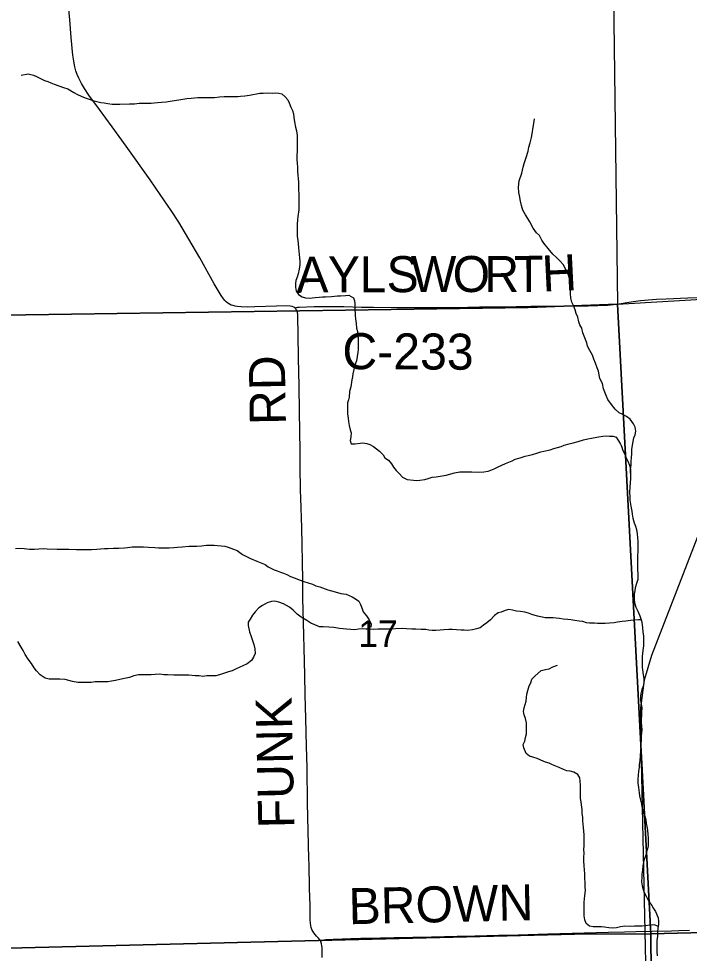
# Model space of a CAD drawing. Extents: x 0 to 34, y 0 to 22.
# Drawn here: x 4.5 to 5.557, y 15.347 to 16.821 of the extents above; entities that cross this region are included whole.
import ezdxf

# ---------------------------------------------------------------- set-up
doc = ezdxf.new("R2010")
doc.units = 0
for name, color, linetype in [('GM_X_County_Road', 7, 'Continuous'), ('GM_X_County_Road_Text', 7, 'Continuous'), ('GM_X_Minor_River', 7, 'Continuous'), ('GM_X_Rail_Line', 7, 'Continuous'), ('GM_X_Section', 7, 'Continuous'), ('GM_X_Section_Text', 7, 'Continuous'), ('GM_X_Township_Road', 7, 'Continuous'), ('GM_X_Township_Road_Text', 7, 'Continuous')]:
    doc.layers.add(name, color=color, linetype=linetype)

msp = doc.modelspace()

# ---------------------------------------------------------------- linework, layer by layer
at = {"layer": 'GM_X_County_Road'}
for points in [[(4.9354, 16.3647), (4.9339, 16.3655), (4.9312, 16.3666), (4.9283, 16.3672), (4.9222, 16.3676), (4.9066, 16.3673), (4.8725, 16.3662), (4.86, 16.3659), (4.8506, 16.3662), (4.8443, 16.3667), (4.8412, 16.3673), (4.8382, 16.3681), (4.8352, 16.3691), (4.8323, 16.3705), (4.8296, 16.3722), (4.8271, 16.3741), (4.8248, 16.3764), (4.8228, 16.3787), (4.8191, 16.3839), (4.8143, 16.3919), (4.8081, 16.4027), (4.7854, 16.4434), (4.7684, 16.473), (4.7523, 16.4996), (4.7406, 16.5179), (4.7232, 16.5436), (4.7072, 16.5665), (4.6693, 16.6197), (4.6475, 16.65), (4.6275, 16.6777), (4.6108, 16.7001), (4.6038, 16.7105), (4.599, 16.7186), (4.5948, 16.7269), (4.5923, 16.7327), (4.5903, 16.7386), (4.5886, 16.7446), (4.5867, 16.7538), (4.5854, 16.7631), (4.5828, 16.791), (4.5805, 16.8188), (4.5781, 16.8467)], [(4.9354, 16.3647), (4.9376, 16.3652), (4.9396, 16.3655), (4.9425, 16.3658), (4.9661, 16.3666), (5.0127, 16.3665), (5.0407, 16.3659), (5.0593, 16.3656), (5.0965, 16.3652), (5.112, 16.365), (5.1369, 16.365), (5.1555, 16.3651), (5.1802, 16.3654), (5.2082, 16.3658), (5.2268, 16.3661), (5.261, 16.3664), (5.3076, 16.3671), (5.3449, 16.3672), (5.3822, 16.3676), (5.3977, 16.3677), (5.4132, 16.3681), (5.4286, 16.3688), (5.4378, 16.3697), (5.447, 16.3709), (5.4623, 16.3734), (5.4807, 16.3762), (5.4931, 16.3775), (5.5055, 16.3783), (5.521, 16.3791), (5.5551, 16.3803), (5.5707, 16.3808)], [(4.9757, 15.3662), (4.9749, 15.3677), (4.9728, 15.3703), (4.9694, 15.3737), (4.9673, 15.3761), (4.9654, 15.3787), (4.9637, 15.3814), (4.9624, 15.3843), (4.9614, 15.3873), (4.9607, 15.3904), (4.9602, 15.3936), (4.9598, 15.3998), (4.9595, 15.4216), (4.9587, 15.4496), (4.9578, 15.4868), (4.9575, 15.4962), (4.9563, 15.5396), (4.9556, 15.5832), (4.9547, 15.6391), (4.9537, 15.6733), (4.9528, 15.7168), (4.9518, 15.7541), (4.9511, 15.7851), (4.9501, 15.8286), (4.9496, 15.8472), (4.9492, 15.869), (4.9488, 15.8876), (4.9481, 15.9063), (4.9479, 15.9342), (4.9476, 15.9653), (4.9469, 15.9902), (4.9462, 16.0181), (4.9448, 16.0646), (4.9446, 16.077), (4.944, 16.1143), (4.9439, 16.1392), (4.9433, 16.1703), (4.9427, 16.2013), (4.942, 16.2417), (4.9412, 16.2852), (4.9406, 16.3225), (4.9403, 16.3505), (4.94, 16.3548), (4.9397, 16.3564), (4.9394, 16.3579), (4.939, 16.3597), (4.9382, 16.3614), (4.9373, 16.3627), (4.9362, 16.364), (4.9354, 16.3647)], [(4.9786, 15.3399), (4.9786, 15.3521), (4.9785, 15.3558), (4.9782, 15.3586), (4.9776, 15.3616), (4.9764, 15.365), (4.9757, 15.3662)]]:
    msp.add_lwpolyline(points, dxfattribs=at)
at = {"layer": 'GM_X_Minor_River'}
for points in [[(4.5037, 16.7314), (4.5151, 16.7337), (4.5231, 16.7314), (4.5289, 16.7291), (4.5342, 16.7264), (4.5407, 16.7234), (4.546, 16.7218), (4.5506, 16.7196), (4.556, 16.7173), (4.5632, 16.7146), (4.5709, 16.7119), (4.5774, 16.71), (4.5869, 16.7043), (4.5927, 16.7013), (4.5984, 16.6986), (4.6049, 16.696), (4.611, 16.6937), (4.6171, 16.6918), (4.6293, 16.6887), (4.6347, 16.688), (4.6404, 16.6868), (4.6473, 16.6857), (4.6595, 16.6857), (4.6747, 16.6864), (4.6824, 16.6864), (4.69, 16.6872), (4.6969, 16.6875), (4.7087, 16.6875), (4.7137, 16.6879), (4.719, 16.6883), (4.7251, 16.689), (4.7327, 16.6898), (4.7419, 16.6913), (4.7526, 16.6925), (4.7652, 16.6947), (4.772, 16.6955), (4.7827, 16.6962), (4.809, 16.6962), (4.8167, 16.6974), (4.8239, 16.6977), (4.8323, 16.6977), (4.8392, 16.6981), (4.8453, 16.6981), (4.8499, 16.6985), (4.8564, 16.6992), (4.864, 16.7), (4.869, 16.7011), (4.8751, 16.7023), (4.88, 16.703), (4.8854, 16.7034), (4.8945, 16.7038), (4.9006, 16.7034), (4.9056, 16.7038), (4.9102, 16.703), (4.9151, 16.7019), (4.9201, 16.6973), (4.9243, 16.6927), (4.9266, 16.6882), (4.9289, 16.6813), (4.9316, 16.676), (4.9335, 16.6707), (4.9339, 16.665), (4.9347, 16.6581), (4.9362, 16.6498), (4.9378, 16.6437), (4.9389, 16.6364), (4.939, 16.6247), (4.939, 16.619), (4.939, 16.6121), (4.9386, 16.6045), (4.9386, 16.5999), (4.939, 16.592), (4.9394, 16.5874), (4.9398, 16.5798), (4.941, 16.5627), (4.9414, 16.5562), (4.9415, 16.5391), (4.9419, 16.5338), (4.9419, 16.5262), (4.9415, 16.5193), (4.9404, 16.5087), (4.9396, 16.5034), (4.9393, 16.4965), (4.9393, 16.4908), (4.9389, 16.4843), (4.9393, 16.4775), (4.9401, 16.4707), (4.9409, 16.4661), (4.9413, 16.4592), (4.9417, 16.4539), (4.9421, 16.449), (4.9428, 16.4433), (4.9432, 16.4379), (4.9432, 16.433), (4.9421, 16.4258), (4.9406, 16.4182), (4.9391, 16.4129), (4.9372, 16.4075), (4.9364, 16.403), (4.9365, 16.3973), (4.9376, 16.3912)], [(5.4649, 16.1038), (5.4645, 16.1106), (5.4657, 16.1163), (5.466, 16.122), (5.4664, 16.1289), (5.4668, 16.1338), (5.4668, 16.141), (5.4679, 16.1479), (5.469, 16.154), (5.4701, 16.1597), (5.472, 16.1646), (5.4732, 16.1703), (5.472, 16.1764), (5.4693, 16.1817), (5.4644, 16.189), (5.4582, 16.1935), (5.4525, 16.1962), (5.4468, 16.1992), (5.4403, 16.2049), (5.4349, 16.2122), (5.4292, 16.2202), (5.4261, 16.2262), (5.4242, 16.2316), (5.4219, 16.2369), (5.4203, 16.2453), (5.4165, 16.2533), (5.4153, 16.259), (5.4142, 16.265), (5.4123, 16.27), (5.4096, 16.2772), (5.4069, 16.2837), (5.4046, 16.2898), (5.4007, 16.2974), (5.3969, 16.3042), (5.3958, 16.3095), (5.3938, 16.3149), (5.3915, 16.3198), (5.3896, 16.3251), (5.3877, 16.3324), (5.3846, 16.3377), (5.3831, 16.3426), (5.3815, 16.3499), (5.3792, 16.3559), (5.3777, 16.3613), (5.3746, 16.3685), (5.3723, 16.3734), (5.3708, 16.3799), (5.37, 16.3871), (5.37, 16.3951), (5.3696, 16.4027), (5.3684, 16.4111), (5.3669, 16.416), (5.3642, 16.4214), (5.3623, 16.4263), (5.3585, 16.4331), (5.3539, 16.4381), (5.3481, 16.4442), (5.3424, 16.4491), (5.3351, 16.4583), (5.3282, 16.4666), (5.3248, 16.4716), (5.3213, 16.4788), (5.3164, 16.483), (5.3114, 16.4902), (5.306, 16.5001), (5.3029, 16.5058), (5.2991, 16.5115), (5.2949, 16.5187), (5.2926, 16.526), (5.291, 16.5328), (5.2895, 16.5416), (5.2887, 16.5465), (5.2883, 16.5549), (5.2894, 16.5648), (5.2936, 16.5769), (5.2955, 16.5864), (5.297, 16.5925), (5.3004, 16.602), (5.3031, 16.6115), (5.3046, 16.618), (5.3065, 16.6248), (5.3087, 16.6332), (5.3099, 16.6389), (5.3114, 16.6495), (5.3121, 16.6556), (5.3133, 16.6625)], [(4.9376, 16.3912), (4.9414, 16.3859), (4.9468, 16.382), (4.9521, 16.3805), (4.9579, 16.3798), (4.9628, 16.3805), (4.9674, 16.3809), (4.9739, 16.3817), (4.9788, 16.382), (4.9838, 16.382), (4.993, 16.3824), (4.9979, 16.3828), (5.0029, 16.3835), (5.0075, 16.3835), (5.0155, 16.3843), (5.0204, 16.3847), (5.0277, 16.3805), (5.0296, 16.3759), (5.03, 16.371), (5.03, 16.3649), (5.0308, 16.3527), (5.0312, 16.3474), (5.032, 16.3398), (5.0328, 16.3326), (5.0343, 16.3272), (5.0347, 16.3219), (5.0351, 16.3155), (5.0355, 16.3109), (5.0355, 16.3056), (5.0351, 16.2991), (5.0348, 16.2945), (5.0336, 16.2881), (5.0325, 16.2809), (5.0302, 16.2744), (5.0287, 16.2675), (5.0268, 16.2603), (5.0261, 16.2558), (5.0253, 16.2512), (5.0235, 16.2398), (5.0216, 16.2329), (5.0212, 16.2238), (5.0201, 16.2193), (5.0185, 16.2147), (5.0186, 16.1976), (5.0194, 16.1904), (5.0201, 16.1854), (5.0213, 16.1789), (5.0228, 16.1725), (5.024, 16.1675), (5.0236, 16.1611), (5.0229, 16.1554), (5.0244, 16.1504), (5.0305, 16.15), (5.0382, 16.1512), (5.0427, 16.1516), (5.0488, 16.1508), (5.0538, 16.1489), (5.0595, 16.1462), (5.0687, 16.1386), (5.0748, 16.1329), (5.0775, 16.128), (5.0829, 16.1242), (5.0878, 16.1185), (5.0909, 16.1131), (5.0951, 16.1082), (5.0997, 16.1032), (5.1051, 16.0975), (5.1127, 16.0937), (5.1223, 16.0926), (5.128, 16.0922), (5.1326, 16.0926), (5.1402, 16.0937), (5.1459, 16.0956), (5.152, 16.0975), (5.1581, 16.0983), (5.1741, 16.1009), (5.1871, 16.1043), (5.1955, 16.1058), (5.2047, 16.1062), (5.2146, 16.1058), (5.2249, 16.1054), (5.2333, 16.1062), (5.2401, 16.1073), (5.2459, 16.1089), (5.2508, 16.1115), (5.2562, 16.1138), (5.2676, 16.1191), (5.2726, 16.121), (5.2783, 16.1233), (5.2828, 16.1259), (5.2905, 16.1282), (5.2985, 16.1305), (5.3034, 16.132), (5.3103, 16.1335), (5.3172, 16.1354), (5.3233, 16.1373), (5.3282, 16.1385), (5.3378, 16.1407), (5.3439, 16.1426), (5.3496, 16.1442), (5.3553, 16.1461)], [(5.3553, 16.1461), (5.3603, 16.148), (5.3679, 16.1499), (5.3744, 16.1517), (5.382, 16.1536), (5.3908, 16.1563), (5.3976, 16.1578), (5.403, 16.159), (5.4144, 16.1612), (5.4209, 16.1624), (5.427, 16.1627), (5.4316, 16.1624), (5.4373, 16.162), (5.4423, 16.1608), (5.4446, 16.1563), (5.4484, 16.1509), (5.4507, 16.1464), (5.4526, 16.1399), (5.4557, 16.1338), (5.4572, 16.1289), (5.4603, 16.1228), (5.463, 16.1167), (5.4645, 16.1095), (5.4649, 16.103), (5.4646, 16.0954), (5.4638, 16.0817), (5.4631, 16.0737), (5.4635, 16.0661), (5.4639, 16.0612), (5.4654, 16.0521), (5.4666, 16.0441), (5.4674, 16.0391), (5.4682, 16.0327), (5.4705, 16.0258), (5.4724, 16.0205), (5.4739, 16.0148), (5.4751, 16.0083), (5.4759, 16.0019), (5.4762, 15.9965), (5.4763, 15.981), (5.4759, 15.9737), (5.4759, 15.9692), (5.4756, 15.9604), (5.4756, 15.9536), (5.4764, 15.9437), (5.476, 15.9361), (5.4741, 15.93), (5.4722, 15.9228), (5.4715, 15.9182), (5.4707, 15.9129), (5.4704, 15.9053), (5.4711, 15.8992), (5.4731, 15.8924), (5.4761, 15.8863), (5.4796, 15.8787), (5.4819, 15.8711), (5.483, 15.8654), (5.4838, 15.8596), (5.4842, 15.8539), (5.485, 15.8467), (5.4854, 15.8399), (5.485, 15.8315), (5.4839, 15.8243), (5.4832, 15.8148), (5.4832, 15.798), (5.4836, 15.7935), (5.4848, 15.7859), (5.4859, 15.7802), (5.4859, 15.7749), (5.4852, 15.7691), (5.4825, 15.7627), (5.481, 15.7562), (5.4806, 15.7517), (5.4803, 15.7456), (5.4814, 15.7395), (5.4826, 15.7338), (5.4818, 15.7266), (5.4819, 15.7212), (5.4815, 15.7163), (5.4815, 15.711), (5.4819, 15.7049), (5.4823, 15.6992), (5.4819, 15.6946), (5.4815, 15.6889), (5.4816, 15.6825), (5.4812, 15.6775), (5.4808, 15.6718), (5.4805, 15.6669), (5.4797, 15.6577), (5.4793, 15.6509), (5.4786, 15.644), (5.4782, 15.6395), (5.4771, 15.6338), (5.4767, 15.6277), (5.4764, 15.6212), (5.4764, 15.6152), (5.4772, 15.6083), (5.4783, 15.5996), (5.4791, 15.595), (5.4806, 15.5882), (5.4818, 15.5821)], [(4.4951, 15.9853), (4.502, 15.9857), (4.5088, 15.9853), (4.5169, 15.9842), (4.5249, 15.9842), (4.5317, 15.9845), (4.5398, 15.9849), (4.5451, 15.9845), (4.5607, 15.9841), (4.568, 15.9838), (4.5791, 15.9841), (4.5909, 15.9837), (4.6146, 15.9837), (4.6233, 15.9841), (4.6291, 15.9845), (4.6355, 15.9852), (4.6405, 15.9852), (4.6497, 15.9856), (4.6577, 15.9856), (4.6668, 15.986), (4.6718, 15.9864), (4.6787, 15.9879), (4.6836, 15.9879), (4.6966, 15.9879), (4.7046, 15.9871), (4.7149, 15.9867), (4.7206, 15.986), (4.726, 15.9859), (4.7313, 15.9863), (4.7374, 15.9863), (4.7447, 15.9867), (4.7504, 15.9871), (4.758, 15.9878), (4.7687, 15.9886), (4.7809, 15.9886), (4.7882, 15.9893), (4.7962, 15.9901), (4.8027, 15.9905), (4.8084, 15.9905), (4.8134, 15.9897), (4.8191, 15.9893), (4.8248, 15.9886), (4.8302, 15.9874), (4.8386, 15.984), (4.8447, 15.9817), (4.8531, 15.9756), (4.8657, 15.9691), (4.8756, 15.9649), (4.8886, 15.9596), (4.8936, 15.9562), (4.9028, 15.9516), (4.9077, 15.9501), (4.9127, 15.9478), (4.9177, 15.9463), (4.923, 15.944), (4.9287, 15.941), (4.936, 15.9383), (4.9421, 15.9356), (4.9494, 15.9333), (4.9631, 15.9288), (4.9685, 15.9261), (4.975, 15.9246), (4.9876, 15.92), (4.9933, 15.9181), (5.0025, 15.9158), (5.0078, 15.9143), (5.0166, 15.9128), (5.0257, 15.909), (5.0311, 15.9059), (5.0361, 15.9021), (5.0391, 15.8968), (5.0411, 15.8915), (5.0434, 15.885), (5.0483, 15.8789), (5.0525, 15.8724), (5.0556, 15.866), (5.0552, 15.861)], [(5.4813, 15.8728), (5.4773, 15.8726), (5.4716, 15.8722), (5.4647, 15.8714), (5.4571, 15.8707), (5.4514, 15.8699), (5.4441, 15.8688), (5.4388, 15.8677), (5.4315, 15.8673), (5.4246, 15.8669), (5.4128, 15.8669), (5.4079, 15.8673), (5.4002, 15.8673), (5.3953, 15.8681), (5.3895, 15.87), (5.3838, 15.8707), (5.3769, 15.8715), (5.3708, 15.8726), (5.3659, 15.873), (5.3586, 15.8734), (5.3525, 15.8746), (5.3475, 15.8753), (5.3426, 15.8757), (5.33, 15.8757), (5.3231, 15.8772), (5.3181, 15.8784), (5.309, 15.881), (5.3036, 15.8829), (5.2983, 15.8845), (5.2914, 15.8856), (5.2849, 15.8864), (5.2788, 15.8879), (5.2727, 15.8887), (5.267, 15.8872), (5.2609, 15.8845), (5.2559, 15.8834), (5.2502, 15.8792), (5.2441, 15.8727), (5.238, 15.8678), (5.2327, 15.8644), (5.2274, 15.8602), (5.2216, 15.8583), (5.2155, 15.8568), (5.2079, 15.856), (5.2026, 15.8564), (5.1976, 15.8564), (5.1904, 15.8568), (5.1835, 15.8572), (5.1785, 15.8572), (5.1701, 15.8568), (5.1648, 15.8564), (5.1575, 15.856), (5.1518, 15.856), (5.1468, 15.8564), (5.1419, 15.8572), (5.1346, 15.8572), (5.1262, 15.8576), (5.1197, 15.8576), (5.1117, 15.8583), (5.1045, 15.8587), (5.0839, 15.8576), (5.0785, 15.858), (5.0663, 15.858), (5.0598, 15.8572), (5.0545, 15.8576), (5.0476, 15.858), (5.0427, 15.8584), (5.0358, 15.8576), (5.0301, 15.8569), (5.0236, 15.8573), (5.0167, 15.8576), (5.0117, 15.8584), (5.006, 15.8588), (4.9969, 15.8603), (4.9892, 15.8611), (4.9801, 15.8615), (4.9743, 15.8618), (4.9667, 15.8649), (4.9606, 15.8672), (4.9541, 15.8714), (4.9453, 15.8767), (4.9392, 15.8813), (4.9327, 15.8877), (4.9269, 15.8923), (4.9174, 15.8976), (4.9101, 15.9007), (4.904, 15.9018), (4.8987, 15.9014), (4.8918, 15.8992), (4.8846, 15.895), (4.8789, 15.8916), (4.8728, 15.8851), (4.8686, 15.8798), (4.8648, 15.8737), (4.8617, 15.8688), (4.8618, 15.8634), (4.8637, 15.8535), (4.8664, 15.8463), (4.8687, 15.8398), (4.8706, 15.8338), (4.8721, 15.8269)], [(4.8721, 15.8269), (4.8729, 15.8197), (4.8703, 15.8136), (4.8672, 15.8087), (4.86, 15.8034), (4.8535, 15.7999), (4.8485, 15.798), (4.8421, 15.795), (4.8367, 15.7923), (4.8306, 15.7908), (4.823, 15.7882), (4.8165, 15.7859), (4.8108, 15.784), (4.7967, 15.784), (4.7902, 15.7832), (4.7845, 15.784), (4.778, 15.7844), (4.7681, 15.7851), (4.7589, 15.7855), (4.7444, 15.7855), (4.7345, 15.7859), (4.7287, 15.7859), (4.7226, 15.7867), (4.7154, 15.7863), (4.7089, 15.7856), (4.6891, 15.7856), (4.6818, 15.7841), (4.6746, 15.7818), (4.6666, 15.7799), (4.6593, 15.7784), (4.6528, 15.7768), (4.6463, 15.7761), (4.6406, 15.775), (4.6357, 15.775), (4.6276, 15.7746), (4.6208, 15.7746), (4.6143, 15.7738), (4.5933, 15.7738), (4.5849, 15.7754), (4.5731, 15.7784), (4.5647, 15.7792), (4.5479, 15.7792), (4.5418, 15.7807), (4.5341, 15.786), (4.528, 15.7921), (4.5245, 15.7971), (4.52, 15.8039), (4.515, 15.8104), (4.51, 15.818), (4.5073, 15.8241), (4.5039, 15.8294), (4.4989, 15.8382)], [(5.5084, 15.3895), (5.5074, 15.3896), (5.5025, 15.3916), (5.4948, 15.3908), (5.4891, 15.39), (5.483, 15.3897), (5.4765, 15.3897), (5.4708, 15.3893), (5.4643, 15.3889), (5.4555, 15.3893), (5.4487, 15.3885), (5.4426, 15.387), (5.4357, 15.3863), (5.4303, 15.387), (5.4239, 15.3878), (5.4189, 15.3882), (5.4124, 15.3886), (5.4059, 15.3886), (5.4002, 15.3893), (5.3948, 15.3939), (5.3925, 15.3992), (5.3918, 15.4057), (5.3917, 15.4274), (5.3928, 15.438), (5.3936, 15.4456), (5.3932, 15.4517), (5.3932, 15.4578), (5.3928, 15.4654), (5.3927, 15.4726), (5.392, 15.4779), (5.3916, 15.4852), (5.3912, 15.492), (5.3912, 15.4981), (5.3915, 15.5046), (5.3911, 15.5103), (5.3915, 15.5163), (5.3915, 15.5335), (5.3911, 15.5392), (5.3907, 15.5452), (5.3903, 15.5502), (5.3895, 15.5555), (5.3895, 15.5616), (5.3887, 15.5669), (5.3883, 15.5734), (5.3875, 15.5806), (5.3868, 15.5855), (5.3856, 15.5909), (5.386, 15.5962), (5.386, 15.6019), (5.3856, 15.6068), (5.3856, 15.6118), (5.3852, 15.6179), (5.3848, 15.6236), (5.3817, 15.6289), (5.3756, 15.6323), (5.3695, 15.6338), (5.3641, 15.6346), (5.3588, 15.6365), (5.3523, 15.6396), (5.3469, 15.6418), (5.3416, 15.6437), (5.3366, 15.6464), (5.3309, 15.6479), (5.3233, 15.651), (5.3175, 15.654), (5.3107, 15.6559), (5.3053, 15.6575), (5.3003, 15.6616), (5.2965, 15.6708), (5.2957, 15.6761), (5.298, 15.6814), (5.2991, 15.6871), (5.3006, 15.6928), (5.3006, 15.7099), (5.2991, 15.7172), (5.2971, 15.7225), (5.296, 15.7282), (5.2971, 15.7339), (5.2986, 15.7388), (5.3001, 15.7445), (5.3009, 15.7499), (5.3013, 15.7552), (5.3028, 15.7609), (5.305, 15.7685), (5.3073, 15.7734), (5.3092, 15.7788), (5.3138, 15.7837), (5.3237, 15.7928), (5.3309, 15.7943), (5.3363, 15.7951), (5.3424, 15.7985), (5.3496, 15.8012)], [(5.4818, 15.5821), (5.4833, 15.5748), (5.4853, 15.5676), (5.4872, 15.5627), (5.4887, 15.5573), (5.4895, 15.5516), (5.4907, 15.5471), (5.4914, 15.5402), (5.4922, 15.5345), (5.4926, 15.5284), (5.4926, 15.5216), (5.4923, 15.5159), (5.4915, 15.5113), (5.49, 15.5068), (5.4889, 15.5015), (5.4858, 15.4931), (5.4843, 15.4847), (5.4836, 15.4779), (5.4828, 15.4714), (5.4824, 15.4669), (5.4821, 15.4592), (5.4829, 15.4528), (5.4848, 15.4475), (5.4863, 15.4425), (5.4894, 15.4368), (5.4921, 15.4315), (5.4951, 15.4265), (5.4982, 15.422), (5.5009, 15.4174), (5.5043, 15.4125), (5.5082, 15.4026), (5.5089, 15.3973), (5.5089, 15.3927), (5.5078, 15.3858), (5.5074, 15.3809), (5.5071, 15.3737), (5.5063, 15.3668), (5.5064, 15.3493), (5.5068, 15.3429)]]:
    msp.add_lwpolyline(points, dxfattribs=at)
at = {"layer": 'GM_X_Rail_Line'}
msp.add_lwpolyline([(5.8886, 16.8335), (5.7201, 16.39), (5.498, 15.8164), (5.486, 15.7774), (5.4805, 15.734), (5.4804, 15.6994), (5.4958, 14.9887), (5.5012, 14.6795)], dxfattribs=at)
at = {"layer": 'GM_X_Section'}
for points in [[(6.4908, 17.4246), (5.4312, 17.3835), (5.4444, 16.3706), (5.9855, 16.4024), (6.4997, 16.4098), (6.4977, 16.8178), (6.4908, 16.8178)], [(4.419, 17.3654), (5.4312, 17.3835), (5.4444, 16.3706), (5.3035, 16.3654), (4.4387, 16.3528)], [(5.4444, 16.3706), (5.9855, 16.4024), (6.4997, 16.4098), (6.508, 15.3973), (6.0014, 15.3899), (5.4966, 15.3772)], [(4.4387, 16.3528), (5.3035, 16.3654), (5.4444, 16.3706), (5.4966, 15.3772), (5.3765, 15.3766), (4.4621, 15.354)], [(5.4966, 15.3772), (6.0014, 15.3899), (6.508, 15.3973), (6.5187, 14.3786), (5.5053, 14.3671)], [(4.4621, 15.354), (5.3765, 15.3766), (5.4966, 15.3772), (5.5053, 14.3671), (4.4738, 14.3535)]]:
    msp.add_lwpolyline(points, close=True, dxfattribs=at)
at = {"layer": 'GM_X_Township_Road'}
msp.add_lwpolyline([(4.9757, 15.3662), (4.9786, 15.367), (4.9819, 15.3679), (4.9844, 15.3683), (4.9866, 15.3686), (4.9959, 15.3691), (5.0238, 15.3699), (5.0393, 15.3704), (5.0703, 15.3711), (5.092, 15.3716), (5.151, 15.3727), (5.1914, 15.3737), (5.2193, 15.3741), (5.2566, 15.3751), (5.2876, 15.3758), (5.3342, 15.3771), (5.4298, 15.38), (5.4551, 15.3806), (5.4729, 15.381), (5.4986, 15.3814), (5.5296, 15.3822), (5.5408, 15.3825), (5.5577, 15.383)], dxfattribs=at)

# ---------------------------------------------------------------- texts
at = {"layer": 'GM_X_County_Road_Text'}
for s, height, rotation, p in [('A', 0.0568, 0.9854, (4.9379, 16.3882)), ('Y', 0.0568, 0.1749, (4.9876, 16.3891)), ('L', 0.0568, 0.1221, (5.0376, 16.3892)), ('S', 0.0568, 0.1237, (5.0801, 16.3893)), ('W', 0.0568, 0.1231, (5.1185, 16.3894)), ('O', 0.0568, 0.122, (5.1843, 16.3895)), ('R', 0.0568, 0.1245, (5.2343, 16.3896)), ('T', 0.0568, 0.3972, (5.2813, 16.3897)), ('H', 0.0568, 2.8123, (5.3264, 16.3901)), ('C-233', 0.05682, 359.7239, (5.0103, 16.268)), ('RD', 0.05682, 90.9858, (4.9214, 16.1804)), ('FUNK', 0.05682, 91.2061, (4.9347, 15.5444))]:
    msp.add_text(s, height=height, rotation=rotation, dxfattribs=at).set_placement(p)
at = {"layer": 'GM_X_Section_Text'}
msp.add_text('17', height=0.04186, rotation=0, dxfattribs=at).set_placement((5.0354, 15.8298))
at = {"layer": 'GM_X_Township_Road_Text'}
msp.add_text('BROWN', height=0.05682, rotation=1.2895, dxfattribs=at).set_placement((5.0208, 15.3924))

doc.saveas('drawing.dxf')
